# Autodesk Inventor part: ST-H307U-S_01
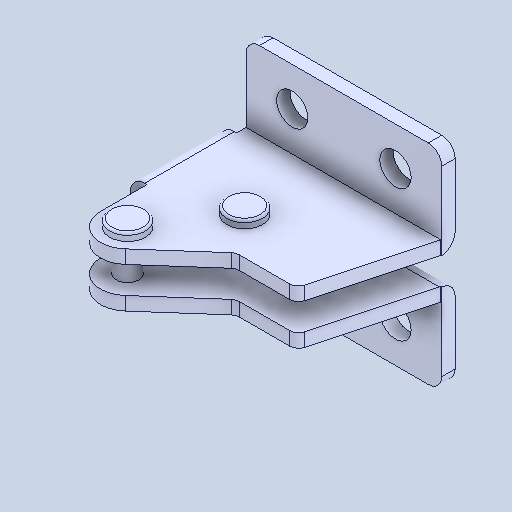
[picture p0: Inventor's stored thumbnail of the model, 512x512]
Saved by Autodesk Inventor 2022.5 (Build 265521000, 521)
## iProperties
Created: 2024-07
Part Number: ST-H307U-S_01
Material: 一般
Document SubType Name: Modeling
Designer: ImaoCorp
Density: 1 g/cm^3
Appearance: 既定
Author: ImaoCorp
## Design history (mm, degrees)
feature "ST-H307U-S_01"
node "ソリッド1"
